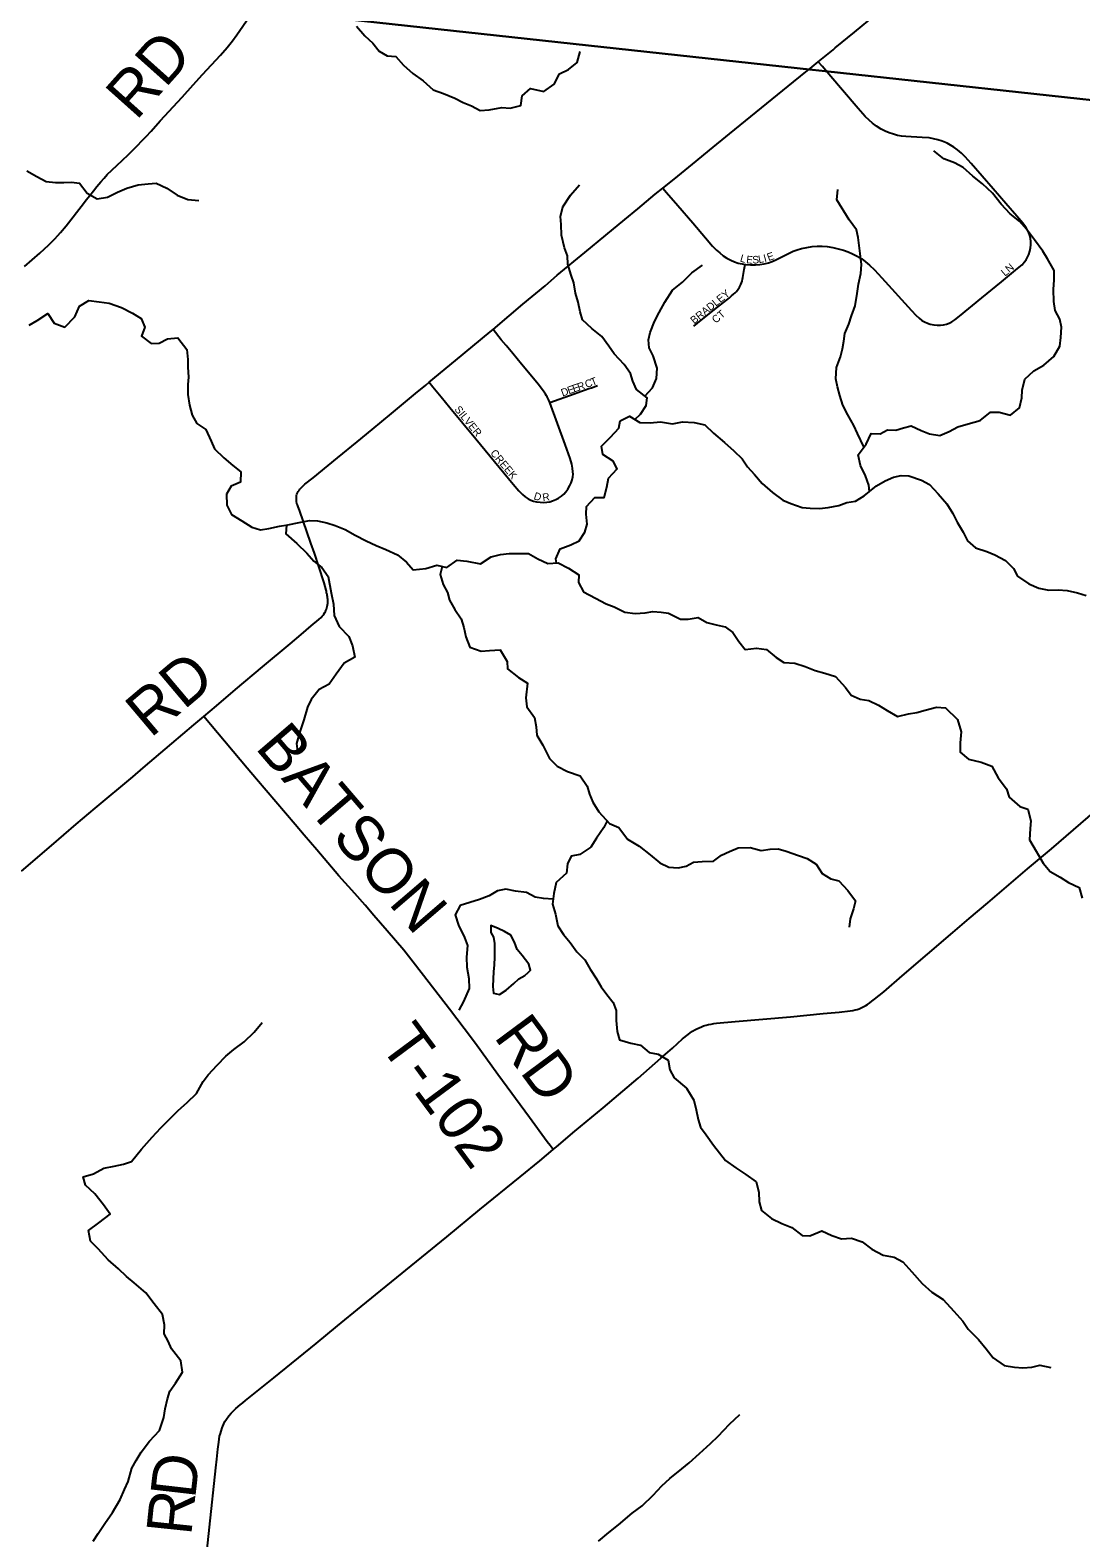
# Model space of a CAD drawing. Extents: x 1442749 to 1756758, y 235267 to 677782.
# Drawn here: x 1590164 to 1597135, y 500562 to 510563 of the extents above; entities that cross this region are included whole.
import ezdxf

# ---------------------------------------------------------------- set-up
doc = ezdxf.new("R2010")
doc.units = 0
for name, color, linetype in [('GM_X_County_Road', 7, 'Continuous'), ('GM_X_County_Road_Text', 7, 'Continuous'), ('GM_X_Minor_Lake', 7, 'Continuous'), ('GM_X_Minor_River', 7, 'Continuous'), ('GM_X_Township', 7, 'Continuous'), ('GM_X_Township_Road', 7, 'Continuous'), ('GM_X_Township_Road_Text', 7, 'Continuous'), ('GM_X_Township_Subdivision', 7, 'Continuous'), ('GM_X_Township_Subdivision_Text', 7, 'Continuous')]:
    doc.layers.add(name, color=color, linetype=linetype)

msp = doc.modelspace()

# ---------------------------------------------------------------- linework, layer by layer
at = {"layer": 'GM_X_County_Road'}
for points in [[(1593633, 503137), (1593656, 503156), (1593778, 503260), (1593965, 503415), (1594198, 503612), (1594349, 503743), (1594425, 503810), (1594493, 503871), (1594529, 503901), (1594543, 503911), (1594559, 503922), (1594574, 503931), (1594587, 503938), (1594602, 503946), (1594618, 503952), (1594632, 503958), (1594649, 503963), (1594665, 503966), (1594682, 503970), (1594699, 503973), (1594718, 503975), (1594842, 503986), (1595208, 504018), (1595426, 504039), (1595531, 504049), (1595605, 504058), (1595622, 504060), (1595637, 504064), (1595651, 504067), (1595665, 504072), (1595686, 504081), (1595708, 504093), (1595720, 504100), (1595736, 504110), (1595749, 504121), (1595767, 504134), (1595827, 504184), (1595950, 504289), (1596286, 504577), (1596395, 504671), (1596518, 504775), (1596782, 505000), (1596940, 505133), (1597280, 505427)], [(1591311, 500238), (1591396, 501027), (1591402, 501083), (1591410, 501151), (1591415, 501197), (1591418, 501216), (1591421, 501236), (1591426, 501253), (1591430, 501269), (1591437, 501291), (1591442, 501303), (1591449, 501318), (1591456, 501333), (1591467, 501350), (1591482, 501371), (1591498, 501389), (1591514, 501405), (1591529, 501419), (1591557, 501443), (1591574, 501457), (1591592, 501472), (1591781, 501624), (1592061, 501852), (1592203, 501968), (1592361, 502097), (1592928, 502559), (1593148, 502740), (1593416, 502957), (1593545, 503063), (1593633, 503137)]]:
    msp.add_lwpolyline(points, dxfattribs=at)
at = {"layer": 'GM_X_Minor_Lake'}
for points in [[(1593468, 504312), (1593484, 504327), (1593472, 504367), (1593429, 504424), (1593395, 504464), (1593378, 504514), (1593352, 504559), (1593310, 504583), (1593268, 504604), (1593221, 504623), (1593220, 504578), (1593238, 504546), (1593245, 504504), (1593244, 504414)], [(1593244, 504414), (1593243, 504362), (1593239, 504317), (1593236, 504271), (1593234, 504219), (1593237, 504175), (1593277, 504165), (1593322, 504194), (1593374, 504238), (1593407, 504269), (1593445, 504291), (1593468, 504312)]]:
    msp.add_lwpolyline(points, dxfattribs=at)
at = {"layer": 'GM_X_Minor_River'}
for points in [[(1592330, 510590), (1592385, 510525), (1592437, 510476), (1592480, 510424), (1592532, 510393), (1592590, 510388), (1592641, 510331), (1592703, 510275), (1592772, 510226), (1592838, 510167), (1592906, 510142), (1592981, 510111), (1593037, 510082), (1593091, 510062), (1593149, 510029), (1593209, 510034), (1593293, 510049), (1593349, 510045), (1593420, 510064), (1593428, 510128), (1593483, 510175), (1593573, 510156), (1593640, 510204), (1593677, 510273), (1593735, 510303), (1593794, 510348), (1593813, 510422)], [(1595733, 507503), (1595729, 507544), (1595707, 507607), (1595674, 507675), (1595657, 507746), (1595710, 507817), (1595743, 507887), (1595803, 507886), (1595853, 507912), (1595907, 507909), (1595958, 507925), (1596010, 507938), (1596076, 507907), (1596130, 507885), (1596200, 507874), (1596262, 507901), (1596320, 507931), (1596387, 507952), (1596467, 507973), (1596536, 508030), (1596594, 508030), (1596668, 508009), (1596729, 508058), (1596744, 508124), (1596746, 508174), (1596763, 508248), (1596824, 508302), (1596889, 508341), (1596957, 508399), (1596996, 508466), (1597003, 508524), (1597006, 508593), (1596996, 508645), (1596965, 508703), (1596956, 508764), (1596953, 508842), (1596959, 508906), (1596958, 508968), (1596913, 509045), (1596882, 509097), (1596828, 509172), (1596775, 509243), (1596730, 509294), (1596666, 509345), (1596607, 509409), (1596549, 509482), (1596482, 509543), (1596418, 509594), (1596355, 509653), (1596297, 509682), (1596227, 509709), (1596160, 509762)], [(1590142, 509630), (1590207, 509593), (1590271, 509558), (1590331, 509552), (1590387, 509553), (1590439, 509554), (1590491, 509548), (1590543, 509481), (1590608, 509444), (1590677, 509455), (1590743, 509489), (1590806, 509514), (1590880, 509537), (1590946, 509543), (1591000, 509548), (1591070, 509515), (1591140, 509468), (1591210, 509439), (1591282, 509434)], [(1594175, 507981), (1594213, 508015), (1594252, 508073), (1594258, 508123), (1594187, 508180), (1594162, 508234), (1594146, 508286), (1594105, 508345), (1594039, 508416), (1594004, 508467), (1593957, 508531), (1593891, 508584), (1593828, 508641), (1593812, 508695), (1593799, 508758), (1593782, 508818), (1593772, 508886), (1593753, 508937), (1593732, 509011), (1593730, 509065), (1593709, 509118), (1593690, 509204), (1593687, 509274), (1593683, 509327), (1593698, 509391), (1593749, 509468), (1593808, 509536)], [(1595696, 507799), (1595653, 507888), (1595629, 507940), (1595588, 508011), (1595557, 508076), (1595537, 508140), (1595520, 508198), (1595509, 508249), (1595513, 508325), (1595540, 508395), (1595553, 508449), (1595562, 508499), (1595570, 508551), (1595595, 508613), (1595614, 508669), (1595637, 508735), (1595652, 508815), (1595660, 508877), (1595675, 508949), (1595680, 509009), (1595671, 509081), (1595665, 509135), (1595658, 509188), (1595647, 509238), (1595597, 509305), (1595515, 509438), (1595522, 509506)], [(1594242, 508135), (1594293, 508190), (1594320, 508252), (1594325, 508320), (1594298, 508403), (1594270, 508455), (1594267, 508508), (1594278, 508558), (1594307, 508630), (1594337, 508691), (1594374, 508759), (1594425, 508839), (1594492, 508892), (1594553, 508954), (1594624, 509003)], [(1590157, 508607), (1590210, 508638), (1590281, 508684), (1590322, 508619), (1590394, 508592), (1590461, 508662), (1590492, 508733), (1590554, 508769), (1590622, 508760), (1590688, 508753), (1590770, 508724), (1590842, 508685), (1590900, 508651), (1590925, 508592), (1590902, 508532), (1590966, 508485), (1591020, 508487), (1591076, 508516), (1591143, 508523), (1591204, 508444), (1591211, 508378), (1591210, 508328), (1591214, 508262), (1591211, 508212), (1591210, 508146), (1591221, 508075), (1591239, 508009), (1591270, 507954), (1591330, 507914), (1591365, 507837), (1591386, 507785), (1591448, 507726), (1591509, 507675), (1591561, 507634), (1591560, 507564), (1591498, 507537), (1591467, 507485), (1591468, 507413), (1591499, 507350), (1591569, 507309), (1591635, 507266), (1591691, 507248), (1591747, 507257), (1591819, 507272), (1591873, 507282), (1591948, 507297), (1592018, 507310), (1592070, 507309), (1592132, 507295), (1592188, 507278), (1592254, 507251), (1592321, 507212), (1592393, 507175), (1592459, 507144), (1592523, 507118), (1592600, 507083)], [(1593655, 507029), (1593652, 507057), (1593681, 507122), (1593752, 507148), (1593806, 507175), (1593843, 507233), (1593860, 507287), (1593854, 507353), (1593855, 507403), (1593910, 507463), (1593972, 507462), (1593989, 507532), (1594000, 507592), (1594058, 507652), (1594033, 507704), (1593963, 507747), (1593954, 507803), (1594015, 507863), (1594070, 507922), (1594078, 507972), (1594141, 508002), (1594210, 507961), (1594278, 507958), (1594347, 507965), (1594425, 507952), (1594491, 507964), (1594569, 507961), (1594641, 507944), (1594697, 507889), (1594770, 507828), (1594833, 507773), (1594887, 507720), (1594924, 507666), (1594970, 507615), (1595021, 507556), (1595089, 507495), (1595158, 507446), (1595210, 507422), (1595286, 507397), (1595340, 507392), (1595400, 507390), (1595458, 507397), (1595529, 507410), (1595583, 507430), (1595639, 507439), (1595698, 507474), (1595779, 507540), (1595837, 507573), (1595892, 507598), (1595942, 507608), (1595994, 507607), (1596078, 507578), (1596132, 507548), (1596189, 507487), (1596246, 507420), (1596286, 507357), (1596315, 507299), (1596354, 507232), (1596382, 507176), (1596437, 507129), (1596511, 507104), (1596565, 507083), (1596635, 507044), (1596688, 506992), (1596714, 506941), (1596789, 506890), (1596857, 506861), (1596923, 506849), (1596985, 506850), (1597045, 506847), (1597113, 506830), (1597171, 506812)], [(1591864, 507280), (1591861, 507221), (1591934, 507158), (1591999, 507094), (1592045, 507041), (1592098, 506998), (1592142, 506939), (1592161, 506831), (1592176, 506755), (1592181, 506680), (1592214, 506608), (1592279, 506541), (1592303, 506478), (1592318, 506404), (1592247, 506365), (1592194, 506291), (1592147, 506225), (1592081, 506190), (1592028, 506124), (1592005, 506071), (1591980, 505987), (1591953, 505909), (1591930, 505831), (1591939, 505760)], [(1592600, 507083), (1592660, 507034), (1592706, 506983), (1592790, 506992), (1592862, 507013), (1592928, 506999), (1592997, 507048), (1593061, 507041), (1593151, 507022), (1593222, 507070), (1593284, 507085), (1593342, 507092), (1593470, 507091), (1593532, 507056), (1593598, 507025), (1593668, 507030), (1593736, 506995), (1593805, 506950), (1593803, 506898), (1593836, 506838), (1593914, 506795), (1593986, 506758), (1594039, 506737), (1594109, 506702), (1594179, 506693), (1594245, 506697), (1594296, 506706), (1594350, 506702), (1594400, 506695), (1594479, 506656), (1594530, 506655), (1594596, 506667), (1594654, 506634), (1594715, 506619), (1594775, 506604), (1594827, 506568), (1594866, 506507), (1594908, 506454), (1594982, 506464), (1595050, 506455), (1595114, 506402), (1595165, 506369), (1595238, 506364), (1595307, 506342), (1595373, 506315), (1595437, 506298), (1595507, 506275), (1595574, 506202), (1595612, 506152), (1595672, 506125), (1595728, 506116), (1595793, 506085), (1595851, 506051), (1595919, 506010), (1595991, 506027), (1596047, 506036), (1596102, 506052), (1596178, 506071), (1596238, 506068), (1596317, 505991), (1596340, 505909), (1596334, 505836), (1596335, 505774), (1596390, 505727), (1596474, 505708), (1596544, 505680), (1596587, 505603), (1596641, 505530), (1596660, 505476), (1596731, 505413), (1596783, 505396), (1596804, 505318), (1596798, 505267), (1596795, 505193), (1596838, 505117), (1596885, 505038), (1596931, 504983), (1596998, 504944), (1597054, 504908), (1597124, 504875), (1597143, 504804)], [(1592898, 507005), (1592884, 506953), (1592903, 506885), (1592932, 506832), (1592946, 506782), (1592981, 506719), (1593024, 506657), (1593042, 506600), (1593055, 506538), (1593080, 506469), (1593156, 506444), (1593212, 506448), (1593282, 506453), (1593328, 506376), (1593331, 506326), (1593405, 506269), (1593464, 506232), (1593453, 506134), (1593460, 506074), (1593510, 506003), (1593521, 505941), (1593526, 505887), (1593566, 505820), (1593609, 505731), (1593660, 505681), (1593730, 505646), (1593812, 505617), (1593859, 505548), (1593874, 505496), (1593898, 505441), (1593937, 505378), (1594008, 505301), (1594070, 505273), (1594127, 505196), (1594205, 505149), (1594278, 505092), (1594342, 505039), (1594402, 505010), (1594464, 505007), (1594516, 505017), (1594566, 505044), (1594623, 505048), (1594697, 505051), (1594751, 505090), (1594804, 505114), (1594862, 505139), (1594942, 505142), (1595014, 505121), (1595073, 505129), (1595127, 505132), (1595181, 505116), (1595262, 505087), (1595320, 505068), (1595378, 505031), (1595419, 504968), (1595477, 504934), (1595529, 504921), (1595590, 504856), (1595640, 504787), (1595627, 504735), (1595604, 504667), (1595599, 504613)], [(1593993, 505318), (1593970, 505274), (1593921, 505204), (1593884, 505144), (1593811, 505095), (1593753, 505084), (1593729, 505032), (1593722, 504970), (1593653, 504908), (1593638, 504836), (1593629, 504766), (1593650, 504700), (1593665, 504621), (1593703, 504563), (1593746, 504512), (1593792, 504450), (1593843, 504395), (1593879, 504334), (1593922, 504270), (1593953, 504217), (1593991, 504166), (1594032, 504112), (1594052, 504059), (1594051, 503993), (1594058, 503921), (1594075, 503865), (1594149, 503844), (1594213, 503829), (1594271, 503782), (1594331, 503771), (1594396, 503731), (1594408, 503666), (1594437, 503614), (1594519, 503545)], [(1593633, 504799), (1593569, 504803), (1593515, 504812), (1593456, 504842), (1593384, 504851), (1593320, 504864), (1593265, 504853), (1593209, 504821), (1593146, 504796), (1593082, 504777), (1593016, 504757), (1592983, 504695), (1593006, 504627), (1593045, 504544), (1593065, 504492), (1593060, 504414), (1593061, 504348), (1593074, 504273), (1593077, 504205), (1593040, 504119), (1593007, 504063)], [(1591312, 503590), (1591345, 503633), (1591404, 503697), (1591463, 503756), (1591515, 503802), (1591584, 503853), (1591651, 503916), (1591704, 503980)], [(1590782, 503040), (1590836, 503059), (1590903, 503141), (1590973, 503220), (1591030, 503281), (1591081, 503333), (1591146, 503396), (1591206, 503450), (1591267, 503509), (1591312, 503590)], [(1594519, 503545), (1594568, 503466), (1594583, 503400), (1594596, 503336), (1594612, 503285), (1594649, 503235), (1594698, 503166), (1594777, 503065), (1594845, 503016), (1594912, 502971), (1594980, 502924), (1594999, 502855), (1595000, 502791), (1595017, 502733), (1595083, 502680), (1595152, 502647), (1595218, 502620), (1595286, 502567), (1595338, 502566), (1595417, 502599), (1595482, 502568), (1595546, 502546), (1595614, 502549), (1595684, 502526), (1595748, 502477), (1595823, 502436), (1595897, 502423), (1595955, 502392), (1596014, 502327), (1596082, 502248), (1596147, 502191), (1596221, 502142), (1596292, 502065), (1596353, 501998), (1596388, 501945), (1596456, 501878), (1596507, 501816), (1596554, 501755), (1596626, 501706), (1596696, 501695), (1596750, 501690), (1596810, 501695), (1596864, 501707), (1596936, 501692)], [(1590582, 500539), (1590616, 500591), (1590659, 500657), (1590711, 500730), (1590760, 500816), (1590789, 500883), (1590814, 500935), (1590839, 501023), (1590868, 501075), (1590900, 501131), (1590956, 501202), (1591023, 501273), (1591050, 501359), (1591059, 501417), (1591076, 501483), (1591090, 501535), (1591129, 501587), (1591174, 501660), (1591163, 501736), (1591102, 501815), (1591079, 501866), (1591053, 501916), (1591056, 501974), (1591041, 502043), (1590986, 502114), (1590931, 502186), (1590853, 502254), (1590802, 502296), (1590750, 502347), (1590681, 502406), (1590616, 502479), (1590564, 502530), (1590551, 502600), (1590620, 502651), (1590695, 502709), (1590650, 502771), (1590593, 502844), (1590531, 502901), (1590516, 502957), (1590584, 502977), (1590653, 503014), (1590721, 503027), (1590782, 503040)], [(1593935, 500540), (1594004, 500597), (1594067, 500649), (1594158, 500726), (1594225, 500773), (1594298, 500844), (1594355, 500907), (1594408, 500955), (1594487, 501020), (1594537, 501059), (1594604, 501121), (1594678, 501188), (1594728, 501237), (1594804, 501315), (1594873, 501380)]]:
    msp.add_lwpolyline(points, dxfattribs=at)
at = {"layer": 'GM_X_Township'}
for points in [[(1607409, 509023), (1601349, 509660), (1598207, 509991), (1595438, 510291), (1595355, 510300), (1591670, 510701), (1587291, 511156), (1584741, 511410), (1583705, 511521), (1580873, 511825), (1577466, 512312), (1577336, 518378), (1577247, 522507)], [(1573762, 498986), (1574679, 502300), (1575144, 503972), (1577400, 512074), (1577466, 512312), (1580873, 511825), (1583705, 511521), (1584741, 511410), (1587291, 511156), (1591670, 510701), (1595355, 510300), (1595438, 510291), (1598207, 509991), (1601349, 509660), (1607409, 509023), (1609267, 508822), (1609586, 508788), (1610595, 504741), (1611751, 500101)]]:
    msp.add_lwpolyline(points, dxfattribs=at)
at = {"layer": 'GM_X_Township_Road'}
for points in [[(1595392, 510352), (1595426, 510379), (1595491, 510433), (1595506, 510446), (1595634, 510549), (1595773, 510664), (1595854, 510731), (1595937, 510800), (1596022, 510872), (1596177, 510998), (1596453, 511219), (1596704, 511420), (1596836, 511527), (1596916, 511592)], [(1590126, 508996), (1590227, 509084), (1590288, 509139), (1590308, 509159), (1590328, 509178), (1590348, 509200), (1590365, 509220), (1590403, 509265), (1590517, 509413), (1590536, 509437), (1590559, 509467), (1590584, 509498), (1590606, 509525), (1590632, 509556), (1590655, 509581), (1590675, 509605), (1590738, 509666), (1590813, 509736), (1590848, 509770), (1590933, 509857), (1590966, 509893), (1591027, 509961), (1591172, 510118), (1591246, 510201), (1591308, 510268), (1591426, 510396), (1591471, 510448), (1591506, 510492), (1591535, 510532), (1591618, 510654)], [(1594361, 509515), (1594436, 509575), (1594583, 509695), (1594672, 509768), (1594804, 509875), (1595194, 510191), (1595311, 510287), (1595339, 510309), (1595392, 510352)], [(1593235, 508577), (1593343, 508669), (1593433, 508745), (1593580, 508867), (1593661, 508938), (1593843, 509088), (1593983, 509202), (1594109, 509307), (1594195, 509377), (1594311, 509474), (1594361, 509515)], [(1592811, 508227), (1592986, 508371), (1593102, 508467), (1593216, 508561), (1593235, 508577)], [(1591316, 506010), (1591400, 506080), (1591527, 506189), (1591705, 506340), (1591888, 506493), (1591961, 506554), (1592029, 506611), (1592080, 506653), (1592094, 506667), (1592101, 506675), (1592107, 506682), (1592113, 506690), (1592119, 506699), (1592123, 506707), (1592126, 506714), (1592129, 506722), (1592132, 506730), (1592134, 506740), (1592137, 506750), (1592138, 506761), (1592138, 506770), (1592138, 506779), (1592138, 506786), (1592137, 506797), (1592136, 506807), (1592135, 506813), (1592134, 506821), (1592131, 506831), (1592129, 506842), (1592128, 506849), (1592114, 506896), (1592080, 507006), (1592050, 507093), (1592027, 507161), (1591950, 507378), (1591941, 507402), (1591937, 507414), (1591934, 507424), (1591932, 507437), (1591930, 507449), (1591930, 507462), (1591931, 507476), (1591934, 507485), (1591938, 507494), (1591943, 507502), (1591948, 507510), (1591953, 507518), (1591959, 507525), (1591966, 507532), (1591972, 507538), (1591980, 507545), (1591987, 507552), (1592041, 507594), (1592141, 507675), (1592202, 507725), (1592333, 507833), (1592432, 507914), (1592561, 508021), (1592721, 508152), (1592789, 508208), (1592811, 508227)], [(1590106, 504984), (1590306, 505154), (1590470, 505296), (1590596, 505401), (1590844, 505611), (1590914, 505670), (1591104, 505831), (1591250, 505954), (1591316, 506010)], [(1593633, 503137), (1593613, 503165), (1593595, 503189), (1593477, 503351), (1593267, 503636), (1593118, 503840), (1593044, 503940), (1592946, 504068), (1592774, 504291), (1592690, 504400), (1592642, 504459), (1592532, 504589), (1592443, 504690), (1592386, 504758), (1592319, 504835), (1592212, 504954), (1592065, 505126), (1591982, 505223), (1591923, 505293), (1591665, 505595), (1591604, 505668), (1591361, 505957), (1591316, 506010)]]:
    msp.add_lwpolyline(points, dxfattribs=at)
at = {"layer": 'GM_X_Township_Subdivision'}
for points in [[(1594907, 509009), (1594913, 509008), (1594943, 509006), (1594976, 509006), (1595005, 509008), (1595034, 509013), (1595063, 509020), (1595087, 509029), (1595111, 509039), (1595190, 509080), (1595208, 509088), (1595226, 509096), (1595254, 509106), (1595282, 509114), (1595317, 509122), (1595353, 509127), (1595386, 509129), (1595419, 509129), (1595451, 509127), (1595490, 509121), (1595526, 509113), (1595560, 509104), (1595591, 509093), (1595621, 509079), (1595650, 509064), (1595681, 509045), (1595707, 509026), (1595733, 509005), (1595766, 508973), (1595815, 508921), (1596011, 508704), (1596040, 508673), (1596062, 508652), (1596080, 508638), (1596097, 508628), (1596118, 508619), (1596136, 508613), (1596159, 508608), (1596182, 508606), (1596205, 508606), (1596224, 508609), (1596243, 508613), (1596262, 508620), (1596279, 508629), (1596299, 508641), (1596330, 508665), (1596479, 508788), (1596609, 508893), (1596715, 508981), (1596745, 509007), (1596760, 509024), (1596772, 509040), (1596782, 509057), (1596790, 509075), (1596797, 509097), (1596801, 509119), (1596804, 509139), (1596804, 509162), (1596801, 509181), (1596797, 509200), (1596791, 509219), (1596782, 509237), (1596770, 509256), (1596751, 509283), (1596711, 509330), (1596637, 509414), (1596553, 509511), (1596407, 509679), (1596368, 509723), (1596344, 509746), (1596317, 509770), (1596293, 509787), (1596271, 509801), (1596248, 509813), (1596214, 509827), (1596186, 509836), (1596158, 509843), (1596128, 509848), (1596083, 509852), (1595975, 509857), (1595945, 509860), (1595919, 509864), (1595891, 509872), (1595863, 509881), (1595836, 509892), (1595810, 509906), (1595779, 509926), (1595753, 509945), (1595731, 509965), (1595705, 509990), (1595657, 510044), (1595463, 510271), (1595420, 510321), (1595392, 510352)], [(1594361, 509515), (1594386, 509486), (1594461, 509399), (1594560, 509285), (1594645, 509185), (1594692, 509131), (1594717, 509104), (1594739, 509085), (1594762, 509067), (1594787, 509051), (1594813, 509037), (1594837, 509026), (1594862, 509018), (1594887, 509012), (1594907, 509009)], [(1594568, 508599), (1594626, 508647), (1594724, 508725), (1594803, 508788), (1594818, 508800), (1594831, 508811), (1594841, 508821), (1594850, 508829), (1594862, 508845), (1594870, 508858), (1594879, 508876), (1594883, 508887), (1594887, 508898), (1594890, 508911), (1594893, 508923), (1594902, 508975), (1594907, 509009)], [(1593611, 508094), (1593605, 508108), (1593598, 508122), (1593594, 508130), (1593590, 508138), (1593584, 508149), (1593575, 508162), (1593564, 508176), (1593535, 508214), (1593470, 508293), (1593424, 508348), (1593366, 508419), (1593321, 508471), (1593290, 508509), (1593235, 508577)], [(1592811, 508227), (1592836, 508197), (1592890, 508131), (1592948, 508060), (1593120, 507852), (1593183, 507777), (1593245, 507701), (1593368, 507552), (1593407, 507507), (1593430, 507483), (1593448, 507468), (1593467, 507455), (1593485, 507446), (1593504, 507439), (1593524, 507434), (1593547, 507431), (1593567, 507430), (1593591, 507431), (1593611, 507434), (1593630, 507440), (1593652, 507449), (1593670, 507458), (1593689, 507472), (1593704, 507486), (1593718, 507500), (1593732, 507519), (1593745, 507543), (1593753, 507561), (1593760, 507580), (1593764, 507600), (1593766, 507617), (1593765, 507634), (1593763, 507657), (1593757, 507683), (1593746, 507721), (1593713, 507814), (1593611, 508094)], [(1593611, 508094), (1593773, 508150), (1593846, 508177), (1593870, 508185), (1593889, 508191), (1593929, 508205)]]:
    msp.add_lwpolyline(points, dxfattribs=at)

# ---------------------------------------------------------------- texts
at = {"layer": 'GM_X_County_Road_Text'}
for s, rotation, p in [('D', 83.4285, (1591258, 500816)), ('R', 84.0645, (1591232, 500572))]:
    msp.add_text(s, height=300, rotation=rotation, dxfattribs=at).set_placement(p)
at = {"layer": 'GM_X_Township_Road_Text'}
for s, rotation, p in [('RD', 48.246, (1590867, 509958)), ('RD', 40.179, (1590962, 505863)), ('BATSON', 310.5816, (1591651, 505802)), ('T-102', 306.5377, (1592475, 503832)), ('RD', 306.5736, (1593235, 503886))]:
    msp.add_text(s, height=300, rotation=rotation, dxfattribs=at).set_placement(p)
at = {"layer": 'GM_X_Township_Subdivision_Text'}
for s, rotation, p in [('L', 344.0884, (1594870, 509029)), ('E', 353.5987, (1594913, 509018)), ('S', 3.818, (1594957, 509014)), ('L', 10.4865, (1594999, 509017)), ('I', 14.8007, (1595037, 509024)), ('E', 19.0529, (1595063, 509031)), ('LN', 40.6039, (1596632, 508927)), ('BRADLEY', 38.9284, (1594569, 508611)), ('CT', 40.6039, (1594713, 508615)), ('D', 19.2436, (1593696, 508132)), ('E', 19.2593, (1593738, 508147)), ('E', 19.2643, (1593771, 508159)), ('R', 19.2568, (1593804, 508170)), ('C', 20.1875, (1593855, 508188)), ('T', 22.2306, (1593894, 508202)), ('SILVER', 309.2104, (1592976, 508046)), ('CREEK', 309.9338, (1593214, 507756)), ('D', 343.0307, (1593501, 507452)), ('R', 8.231, (1593566, 507438))]:
    msp.add_text(s, height=50, rotation=rotation, dxfattribs=at).set_placement(p)

doc.saveas('drawing.dxf')
